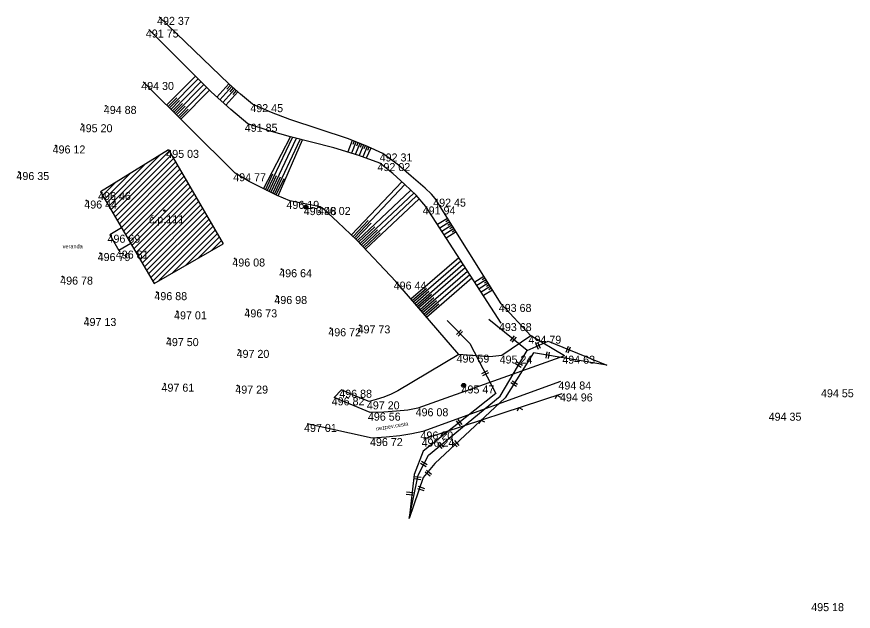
# Model space of a CAD drawing. Extents: x -554123 to -553118, y -1076825 to -1073672.
# Drawn here: x -553552.4 to -553447.8, y -1076688.9 to -1076614.7 of the extents above; entities that cross this region are included whole.
import ezdxf

# ---------------------------------------------------------------- set-up
doc = ezdxf.new("R2010")
doc.units = 0
for name, color, linetype in [('1', 7, 'Continuous'), ('12', 7, 'Continuous'), ('14', 7, 'Continuous'), ('17', 7, 'Continuous'), ('20', 7, 'Continuous'), ('26', 7, 'Continuous'), ('27', 7, 'Continuous'), ('32', 7, 'Continuous'), ('47', 7, 'Continuous'), ('52', 7, 'Continuous'), ('54', 7, 'Continuous'), ('6', 7, 'Continuous'), ('62', 7, 'Continuous')]:
    doc.layers.add(name, color=color, linetype=linetype)

# ---------------------------------------------------------------- blocks, each defined once
blk = doc.blocks.new('POINT_DISPLAY')
blk.add_line((0, 0), (0, 0))
blk = doc.blocks.new('SLB')
at = {"layer": '20'}
for radius in [0.25, 0.158, 0.05]:
    blk.add_circle((0, 0), radius, dxfattribs=at)
blk = doc.blocks.new('T')
at = {"layer": '6'}
blk.add_circle((0, 0), 0.05, dxfattribs=at)
blk = doc.blocks.new('BZ')
at = {"layer": '47'}
blk.add_circle((0, 0), 0.0875, dxfattribs=at)
blk = doc.blocks.new('ROV')
at = {"layer": '62'}
for p, q in [((-0.348, -0.51), (-0.348, 0.51)), ((0, -0.51), (0, 0.51))]:
    blk.add_line(p, q, dxfattribs=at)

msp = doc.modelspace()

# ---------------------------------------------------------------- linework, layer by layer
at = {"layer": '12'}
for p, q in [((-553501.49, -1076667.39), (-553484.18, -1076661.74)), ((-553484.85, -1076661.96), (-553485.08, -1076662.41)), ((-553484.85, -1076661.96), (-553484.41, -1076662.19)), ((-553489.61, -1076663.51), (-553489.83, -1076663.96)), ((-553489.61, -1076663.51), (-553489.16, -1076663.74)), ((-553494.36, -1076665.06), (-553494.59, -1076665.51)), ((-553494.36, -1076665.06), (-553493.91, -1076665.29)), ((-553499.11, -1076666.61), (-553499.34, -1076667.06)), ((-553499.11, -1076666.61), (-553498.67, -1076666.84))]:
    msp.add_line(p, q, dxfattribs=at)
at = {"layer": '14'}
for p, q in [((-553533.39, -1076631.32), (-553541.9, -1076636.58)), ((-553533.39, -1076631.32), (-553526.57, -1076643.06)), ((-553541.9, -1076636.58), (-553535.18, -1076647.99)), ((-553539.26, -1076641.07), (-553540.7, -1076641.92)), ((-553540.7, -1076641.92), (-553539.58, -1076643.9)), ((-553538.1, -1076643.03), (-553539.58, -1076643.9)), ((-553535.18, -1076647.99), (-553526.57, -1076643.06))]:
    msp.add_line(p, q, dxfattribs=at)
at = {"layer": '17'}
for p, q in [((-553483.91, -1076657.03), (-553502.22, -1076663.59)), ((-553484.41, -1076660.25), (-553501.61, -1076666.49)), ((-553508.17, -1076664.14), (-553512.7, -1076662.23)), ((-553507.93, -1076667.31), (-553516.07, -1076665.55))]:
    msp.add_line(p, q, dxfattribs=at)
for points in [[(-553502.22, -1076663.59), (-553503.49, -1076663.82), (-553504.88, -1076663.95), (-553506.46, -1076664.1), (-553508.17, -1076664.14)], [(-553501.61, -1076666.49), (-553502.97, -1076666.8), (-553504.47, -1076667.02), (-553506.17, -1076667.21), (-553507.93, -1076667.31)]]:
    msp.add_lwpolyline(points, dxfattribs=at)
at = {"layer": '26'}
for p, q in [((-553533.62, -1076625.73), (-553530.02, -1076622.1)), ((-553533.27, -1076626.08), (-553529.67, -1076622.45)), ((-553532.91, -1076626.44), (-553529.31, -1076622.8)), ((-553532.56, -1076626.79), (-553528.96, -1076623.16)), ((-553532.2, -1076627.14), (-553528.6, -1076623.51)), ((-553525.85, -1076623.08), (-553527.33, -1076624.73)), ((-553525.47, -1076623.41), (-553526.96, -1076625.07)), ((-553525.66, -1076623.25), (-553526.1, -1076623.74)), ((-553525.29, -1076623.58), (-553525.73, -1076624.08)), ((-553531.85, -1076627.49), (-553528.25, -1076623.86)), ((-553525.1, -1076623.75), (-553526.59, -1076625.41)), ((-553524.73, -1076624.08), (-553526.22, -1076625.75)), ((-553524.92, -1076623.92), (-553525.36, -1076624.41)), ((-553533.45, -1076625.91), (-553532.36, -1076624.82)), ((-553533.09, -1076626.26), (-553532.01, -1076625.17)), ((-553532.74, -1076626.61), (-553531.66, -1076625.52)), ((-553532.38, -1076626.96), (-553531.3, -1076625.87)), ((-553532.03, -1076627.31), (-553530.95, -1076626.23)), ((-553521.5, -1076636.2), (-553518.13, -1076629.71)), ((-553521.05, -1076636.42), (-553517.91, -1076629.76)), ((-553520.6, -1076636.63), (-553517.41, -1076629.88)), ((-553520.15, -1076636.84), (-553516.92, -1076630.01)), ((-553519.69, -1076637.05), (-553516.63, -1076630.08)), ((-553510.42, -1076630.15), (-553511, -1076631.58)), ((-553509.96, -1076630.34), (-553510.53, -1076631.74)), ((-553510.19, -1076630.24), (-553510.36, -1076630.67)), ((-553509.49, -1076630.53), (-553510.05, -1076631.89)), ((-553509.73, -1076630.43), (-553509.89, -1076630.84)), ((-553509.03, -1076630.71), (-553509.57, -1076632.04)), ((-553509.26, -1076630.62), (-553509.43, -1076631.02)), ((-553508.57, -1076630.9), (-553509.1, -1076632.21)), ((-553508.8, -1076630.81), (-553508.96, -1076631.2)), ((-553508.11, -1076631.1), (-553508.67, -1076632.36)), ((-553508.34, -1076631), (-553508.51, -1076631.39)), ((-553521.28, -1076636.31), (-553520.34, -1076634.33)), ((-553520.82, -1076636.52), (-553519.88, -1076634.51)), ((-553520.37, -1076636.74), (-553519.41, -1076634.7)), ((-553519.92, -1076636.95), (-553518.95, -1076634.89)), ((-553510.51, -1076641.95), (-553504.22, -1076635.31)), ((-553510.15, -1076642.29), (-553503.85, -1076635.64)), ((-553509.79, -1076642.64), (-553503.09, -1076636.37)), ((-553509.45, -1076643.01), (-553502.73, -1076636.72)), ((-553509.11, -1076643.37), (-553502.38, -1076637.08)), ((-553508.77, -1076643.74), (-553502.05, -1076637.45)), ((-553510.33, -1076642.12), (-553508.44, -1076640.13)), ((-553498.51, -1076639.88), (-553499.77, -1076640.66)), ((-553498.24, -1076640.3), (-553499.5, -1076641.08)), ((-553498.38, -1076640.09), (-553498.75, -1076640.32)), ((-553509.97, -1076642.47), (-553508.08, -1076640.47)), ((-553509.62, -1076642.82), (-553507.61, -1076640.94)), ((-553509.28, -1076643.19), (-553507.26, -1076641.3)), ((-553497.98, -1076640.72), (-553499.22, -1076641.5)), ((-553497.71, -1076641.15), (-553498.95, -1076641.92)), ((-553498.11, -1076640.51), (-553498.49, -1076640.75)), ((-553497.85, -1076640.94), (-553498.22, -1076641.17)), ((-553497.58, -1076641.36), (-553497.95, -1076641.59)), ((-553508.94, -1076643.55), (-553506.92, -1076641.67)), ((-553497.45, -1076641.57), (-553498.68, -1076642.34)), ((-553503.11, -1076649.94), (-553497.12, -1076644.75)), ((-553502.78, -1076650.32), (-553496.85, -1076645.18)), ((-553502.46, -1076650.7), (-553496.57, -1076645.6)), ((-553502.13, -1076651.07), (-553496.3, -1076646.02)), ((-553501.8, -1076651.45), (-553496.02, -1076646.45)), ((-553501.47, -1076651.83), (-553495.75, -1076646.87)), ((-553501.15, -1076652.21), (-553495.47, -1076647.29)), ((-553493.97, -1076647.13), (-553495.12, -1076647.85)), ((-553493.71, -1076647.56), (-553494.84, -1076648.27)), ((-553493.84, -1076647.34), (-553494.18, -1076647.56)), ((-553502.95, -1076650.13), (-553501.16, -1076648.58)), ((-553493.44, -1076647.98), (-553494.57, -1076648.69)), ((-553493.18, -1076648.4), (-553494.3, -1076649.1)), ((-553493.58, -1076647.77), (-553493.92, -1076647.98)), ((-553493.31, -1076648.19), (-553493.65, -1076648.4)), ((-553493.05, -1076648.61), (-553493.38, -1076648.82)), ((-553502.62, -1076650.51), (-553500.85, -1076648.97)), ((-553502.29, -1076650.89), (-553500.53, -1076649.36)), ((-553492.91, -1076648.83), (-553494.03, -1076649.52)), ((-553501.96, -1076651.26), (-553500.22, -1076649.76)), ((-553501.64, -1076651.64), (-553499.91, -1076650.15)), ((-553501.31, -1076652.02), (-553499.6, -1076650.54))]:
    msp.add_line(p, q, dxfattribs=at)
at = {"layer": '27'}
for p, q in [((-553525.04, -1076634.24), (-553536.54, -1076622.84)), ((-553514.43, -1076638.45), (-553518.24, -1076637.69)), ((-553491.83, -1076650.56), (-553500.05, -1076637.41)), ((-553491.81, -1076652.95), (-553501.24, -1076638.39)), ((-553497.09, -1076656.89), (-553504.99, -1076647.77)), ((-553488.13, -1076654.53), (-553491.83, -1076650.56)), ((-553488.13, -1076654.53), (-553491.75, -1076657.01)), ((-553483.91, -1076657.03), (-553488.13, -1076654.53)), ((-553511.76, -1076661.28), (-553512.7, -1076662.23))]:
    msp.add_line(p, q, dxfattribs=at)
for points in [[(-553522.9, -1076625.61), (-553524.41, -1076624.37), (-553525.86, -1076623.07), (-553534.55, -1076614.71)], [(-553523.48, -1076628.06), (-553525.62, -1076626.3), (-553528.06, -1076624.06), (-553535.84, -1076616.29)], [(-553506.62, -1076631.77), (-553508.54, -1076630.92), (-553510.9, -1076629.96), (-553518.22, -1076627.52), (-553520.52, -1076626.65), (-553522.9, -1076625.61)], [(-553506.99, -1076632.97), (-553509.61, -1076632.02), (-553512.71, -1076631.05), (-553518.13, -1076629.71), (-553520.83, -1076628.95), (-553523.48, -1076628.06)], [(-553500.05, -1076637.41), (-553500.54, -1076636.86), (-553501.32, -1076636.09), (-553503.06, -1076634.59), (-553504.64, -1076633.25), (-553506.62, -1076631.77)], [(-553501.24, -1076638.39), (-553502.46, -1076636.99), (-553503.86, -1076635.63), (-553505.35, -1076634.29), (-553506.99, -1076632.97)], [(-553518.24, -1076637.69), (-553519.81, -1076637), (-553521.4, -1076636.25), (-553523.3, -1076635.26), (-553525.04, -1076634.24)], [(-553504.99, -1076647.77), (-553509.84, -1076642.59), (-553512.22, -1076640.34), (-553513.38, -1076639.28), (-553513.91, -1076638.83), (-553514.43, -1076638.45)], [(-553497.09, -1076656.89), (-553504.73, -1076661.4), (-553505.56, -1076661.83), (-553506.47, -1076662.2), (-553507.42, -1076662.5), (-553508.33, -1076662.73)], [(-553491.75, -1076657.01), (-553492.85, -1076657.13), (-553493.41, -1076657.15), (-553493.97, -1076657.14), (-553497.09, -1076656.89)], [(-553508.33, -1076662.73), (-553509.89, -1076662.14), (-553511.76, -1076661.28)]]:
    msp.add_lwpolyline(points, dxfattribs=at)
at = {"layer": '32'}
for p, q in [((-553540.59, -1076638.81), (-553533.29, -1076631.5)), ((-553540.33, -1076639.25), (-553533.03, -1076631.95)), ((-553540.85, -1076638.36), (-553534.49, -1076632)), ((-553540.07, -1076639.7), (-553532.77, -1076632.4)), ((-553539.8, -1076640.14), (-553532.51, -1076632.84)), ((-553541.11, -1076637.92), (-553536.34, -1076633.15)), ((-553539.54, -1076640.58), (-553532.25, -1076633.29)), ((-553539.28, -1076641.03), (-553531.99, -1076633.74)), ((-553541.38, -1076637.47), (-553538.2, -1076634.29)), ((-553539.02, -1076641.48), (-553531.73, -1076634.18)), ((-553538.76, -1076641.92), (-553531.47, -1076634.63)), ((-553538.49, -1076642.36), (-553531.21, -1076635.08)), ((-553541.64, -1076637.03), (-553540.05, -1076635.44)), ((-553538.23, -1076642.81), (-553530.95, -1076635.53)), ((-553537.97, -1076643.26), (-553530.69, -1076635.97)), ((-553537.71, -1076643.7), (-553530.43, -1076636.42)), ((-553537.44, -1076644.15), (-553530.17, -1076636.87)), ((-553537.18, -1076644.59), (-553529.91, -1076637.31)), ((-553536.92, -1076645.04), (-553529.65, -1076637.76)), ((-553536.66, -1076645.48), (-553529.39, -1076638.21)), ((-553536.4, -1076645.93), (-553529.13, -1076638.66)), ((-553536.13, -1076646.37), (-553528.87, -1076639.1)), ((-553535.87, -1076646.81), (-553528.61, -1076639.55)), ((-553535.61, -1076647.26), (-553528.35, -1076640)), ((-553535.35, -1076647.71), (-553528.09, -1076640.45)), ((-553534.58, -1076647.65), (-553527.83, -1076640.89)), ((-553532.93, -1076646.7), (-553527.57, -1076641.34)), ((-553531.28, -1076645.75), (-553527.31, -1076641.79)), ((-553529.62, -1076644.81), (-553527.05, -1076642.24)), ((-553527.97, -1076643.86), (-553526.79, -1076642.68))]:
    msp.add_line(p, q, dxfattribs=at)
at = {"layer": '62'}
for p, q in [((-553498.57, -1076652.65), (-553495.73, -1076655.49)), ((-553488.55, -1076656.37), (-553493.34, -1076652.49)), ((-553495.73, -1076655.49), (-553492.48, -1076661.73)), ((-553488.55, -1076656.37), (-553485.96, -1076655.21)), ((-553485.96, -1076655.21), (-553478.63, -1076658.19)), ((-553491.95, -1076662.07), (-553488.55, -1076656.37)), ((-553487.76, -1076656.66), (-553491.33, -1076662.3)), ((-553478.63, -1076658.19), (-553487.76, -1076656.66)), ((-553492.48, -1076661.73), (-553501.58, -1076668.95)), ((-553500.9, -1076669.46), (-553491.95, -1076662.07)), ((-553491.33, -1076662.3), (-553500.12, -1076670.47)), ((-553501.58, -1076668.95), (-553502.71, -1076671.85)), ((-553502.21, -1076671.94), (-553500.9, -1076669.46)), ((-553500.12, -1076670.47), (-553501.57, -1076672.24)), ((-553502.71, -1076671.85), (-553503.33, -1076677.38)), ((-553503.33, -1076677.38), (-553502.21, -1076671.94)), ((-553501.57, -1076672.24), (-553503.33, -1076677.38))]:
    msp.add_line(p, q, dxfattribs=at)

# ---------------------------------------------------------------- block references
at = {"layer": '1'}
for p in [(-553534.55, -1076614.71), (-553535.84, -1076616.29), (-553536.54, -1076622.84), (-553522.9, -1076625.61), (-553541.21, -1076625.83), (-553544.2, -1076628.12), (-553523.48, -1076628.06), (-553547.48, -1076630.77), (-553533.39, -1076631.32), (-553506.62, -1076631.77), (-553506.99, -1076632.97), (-553552.1, -1076634.09), (-553525.04, -1076634.24), (-553541.9, -1076636.58), (-553543.65, -1076637.65), (-553518.24, -1076637.69), (-553500.05, -1076637.41), (-553516.22, -1076638.47), (-553514.43, -1076638.45), (-553501.24, -1076638.39), (-553540.7, -1076641.92), (-553526.57, -1076643.06), (-553526.57, -1076643.06), (-553541.94, -1076644.21), (-553539.58, -1076643.9), (-553525.12, -1076644.89), (-553519.26, -1076646.23), (-553546.64, -1076647.15), (-553535.18, -1076647.99), (-553504.99, -1076647.77), (-553534.86, -1076649.09), (-553519.86, -1076649.57), (-553491.83, -1076650.56), (-553532.31, -1076651.49), (-553523.62, -1076651.24), (-553543.62, -1076652.32), (-553513.14, -1076653.6), (-553509.49, -1076653.24), (-553491.81, -1076652.95), (-553533.44, -1076654.83), (-553488.13, -1076654.53), (-553524.61, -1076656.3), (-553497.09, -1076656.89), (-553491.75, -1076657.01), (-553483.91, -1076657.03), (-553533.87, -1076660.52), (-553524.76, -1076660.76), (-553496.51, -1076660.74), (-553484.41, -1076660.25), (-553451.59, -1076661.22), (-553512.7, -1076662.23), (-553511.76, -1076661.28), (-553484.18, -1076661.74), (-553508.33, -1076662.73), (-553508.17, -1076664.14), (-553502.22, -1076663.59), (-553458.13, -1076664.15), (-553516.07, -1076665.55), (-553507.93, -1076667.31), (-553501.61, -1076666.49), (-553501.49, -1076667.39), (-553452.69, -1076687.93)]:
    msp.add_blockref('POINT_DISPLAY', p, dxfattribs=at)
at = {"layer": '14'}
msp.add_blockref('POINT_DISPLAY', (-553526.57, -1076643.06), dxfattribs=at)
at = {"layer": '20'}
for p in [(-553516.22, -1076638.47), (-553496.51, -1076660.74)]:
    msp.add_blockref('SLB', p, dxfattribs=at)
at = {"layer": '32'}
msp.add_blockref('POINT_DISPLAY', (-553541.9, -1076636.58), dxfattribs=at)
at = {"layer": '47'}
msp.add_blockref('BZ', (-553533.93, -1076638.9), dxfattribs=at)
at = {"layer": '52'}
for p, xscale, yscale, rotation in [((-553496.92, -1076654.3), 0.8000012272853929, 0.8000012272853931, -45.000000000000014), ((-553490.43, -1076654.85), 0.7999991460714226, 0.7999991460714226, 140.99189769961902), ((-553487.36, -1076655.84), 0.7999999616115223, 0.7999999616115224, -155.87351522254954), ((-553483.29, -1076656.3), 0.80000085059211, 0.80000085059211, -22.124192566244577), ((-553486.16, -1076656.93), 0.8000011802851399, 0.8000011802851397, 170.48679744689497), ((-553489.66, -1076658.23), 0.8000017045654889, 0.8000017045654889, -120.8157911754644), ((-553493.73, -1076659.32), 0.7999991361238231, 0.7999991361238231, -62.487812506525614), ((-553490.26, -1076660.6), 0.7999998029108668, 0.7999998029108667, -122.33281116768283), ((-553497.19, -1076665.47), 0.8000017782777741, 0.8000017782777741, -141.57124034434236), ((-553499.51, -1076668.31), 0.8000001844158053, 0.8000001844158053, -140.4534116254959), ((-553497.59, -1076668.12), 0.8000018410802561, 0.8000018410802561, -137.09363738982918), ((-553501.42, -1076670.45), 0.8000017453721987, 0.8000017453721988, 62.155748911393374), ((-553501, -1076671.78), 0.8000011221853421, 0.8000011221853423, -129.3245814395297), ((-553502.24, -1076672.19), 0.8000010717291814, 0.8000010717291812, 83.60309079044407), ((-553501.88, -1076673.73), 0.7999997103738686, 0.7999997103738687, -108.90194797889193), ((-553503.24, -1076674.12), 0.8000010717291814, 0.8000010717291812, 83.60309079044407)]:
    msp.add_blockref('ROV', p, dxfattribs=dict(at, xscale=xscale, yscale=yscale, rotation=rotation))
at = {"layer": '6'}
for p in [(-553541.21, -1076625.83), (-553544.2, -1076628.12), (-553547.48, -1076630.77), (-553552.1, -1076634.09), (-553543.65, -1076637.65), (-553541.94, -1076644.21), (-553525.12, -1076644.89), (-553519.26, -1076646.23), (-553546.64, -1076647.15), (-553534.86, -1076649.09), (-553519.86, -1076649.57), (-553532.31, -1076651.49), (-553523.62, -1076651.24), (-553543.62, -1076652.32), (-553513.14, -1076653.6), (-553509.49, -1076653.24), (-553533.44, -1076654.83), (-553524.61, -1076656.3), (-553533.87, -1076660.52), (-553524.76, -1076660.76)]:
    msp.add_blockref('T', p, dxfattribs=at)

# ---------------------------------------------------------------- texts
at = {"layer": '52'}
msp.add_text('veranda', height=0.5, dxfattribs=at).set_placement((-553546.61, -1076643.62))
msp.add_text('nezpev.cesta', height=0.5, rotation=9.4616, dxfattribs=at).set_placement((-553507.41, -1076666.4))
at = {"layer": '54'}
msp.add_text('č.p.111', height=1, dxfattribs=at).set_placement((-553535.82, -1076640.5))
at = {"layer": '6'}
for s, p in [('492 37 ', (-553534.82, -1076615.71)), ('491 75 ', (-553536.22, -1076617.29)), ('494 30 ', (-553536.8, -1076623.84)), ('492 45 ', (-553523.16, -1076626.61)), ('494 88 ', (-553541.47, -1076626.83)), ('495 20 ', (-553544.48, -1076629.12)), ('491 85 ', (-553523.86, -1076629.06)), ('496 12 ', (-553547.87, -1076631.77)), ('495 03 ', (-553533.67, -1076632.32)), ('492 31 ', (-553507, -1076632.77)), ('492 02 ', (-553507.27, -1076633.97)), ('496 35 ', (-553552.39, -1076635.09)), ('494 77 ', (-553525.3, -1076635.24)), ('496 46 ', (-553542.19, -1076637.58)), ('496 44 ', (-553543.91, -1076638.65)), ('496 19 ', (-553518.65, -1076638.69)), ('492 45 ', (-553500.31, -1076638.41)), ('496 48 ', (-553516.49, -1076639.47)), ('496 02 ', (-553514.72, -1076639.45)), ('491 94 ', (-553501.62, -1076639.39)), ('496 69 ', (-553541.01, -1076642.92)), ('496 79 ', (-553542.24, -1076645.21)), ('496 81 ', (-553539.97, -1076644.9)), ('496 08 ', (-553525.41, -1076645.89)), ('496 64 ', (-553519.55, -1076647.23)), ('496 78 ', (-553546.92, -1076648.15)), ('496 44 ', (-553505.25, -1076648.77)), ('496 88 ', (-553535.15, -1076650.09)), ('496 98 ', (-553520.16, -1076650.57)), ('493 68 ', (-553492.12, -1076651.56)), ('497 01 ', (-553532.69, -1076652.49)), ('496 73 ', (-553523.9, -1076652.24)), ('497 13 ', (-553544, -1076653.32)), ('496 72 ', (-553513.42, -1076654.6)), ('497 73 ', (-553509.76, -1076654.24)), ('493 68 ', (-553492.1, -1076653.95)), ('497 50 ', (-553533.71, -1076655.83)), ('494 79 ', (-553488.4, -1076655.53)), ('497 20 ', (-553524.88, -1076657.3)), ('496 59 ', (-553497.39, -1076657.89)), ('495 24 ', (-553492.01, -1076658.01)), ('494 63 ', (-553484.18, -1076658.03)), ('497 61 ', (-553534.26, -1076661.52)), ('497 29 ', (-553525.04, -1076661.76)), ('495 47 ', (-553496.77, -1076661.74)), ('494 84 ', (-553484.66, -1076661.25)), ('494 55 ', (-553451.85, -1076662.22)), ('496 82 ', (-553512.99, -1076663.23)), ('496 88 ', (-553512.05, -1076662.28)), ('494 96 ', (-553484.47, -1076662.74)), ('497 20 ', (-553508.6, -1076663.73)), ('496 56 ', (-553508.47, -1076665.14)), ('496 08 ', (-553502.51, -1076664.59)), ('494 35 ', (-553458.39, -1076665.15)), ('497 01 ', (-553516.45, -1076666.55)), ('496 72 ', (-553508.21, -1076668.31)), ('496 20 ', (-553501.9, -1076667.49)), ('496 24 ', (-553501.76, -1076668.39)), ('495 18 ', (-553453.07, -1076688.93))]:
    msp.add_text(s, height=1, dxfattribs=at).set_placement(p)

doc.saveas('drawing.dxf')
